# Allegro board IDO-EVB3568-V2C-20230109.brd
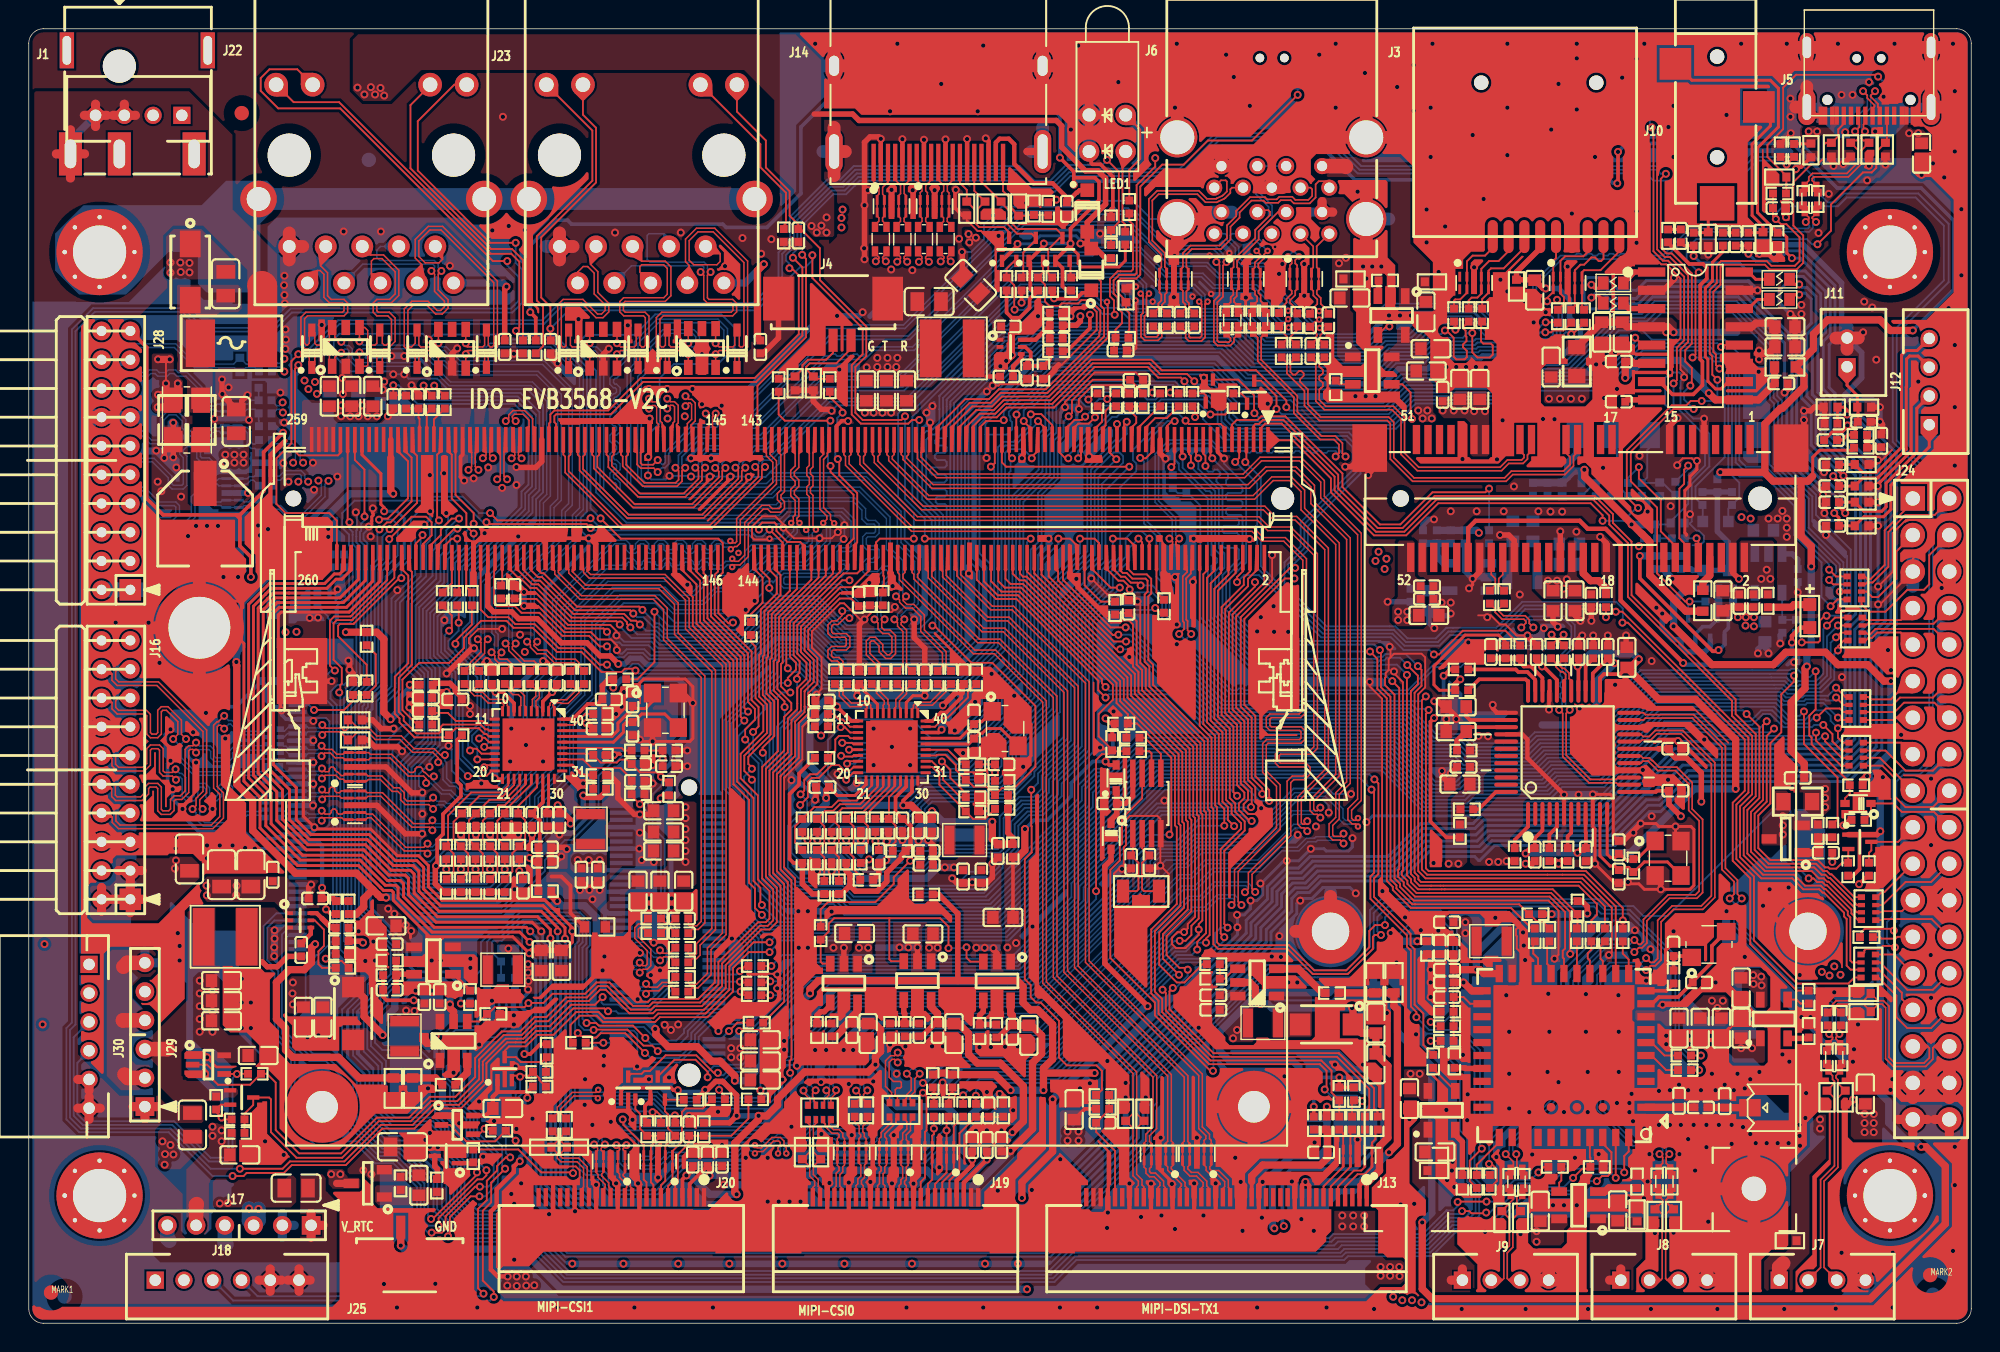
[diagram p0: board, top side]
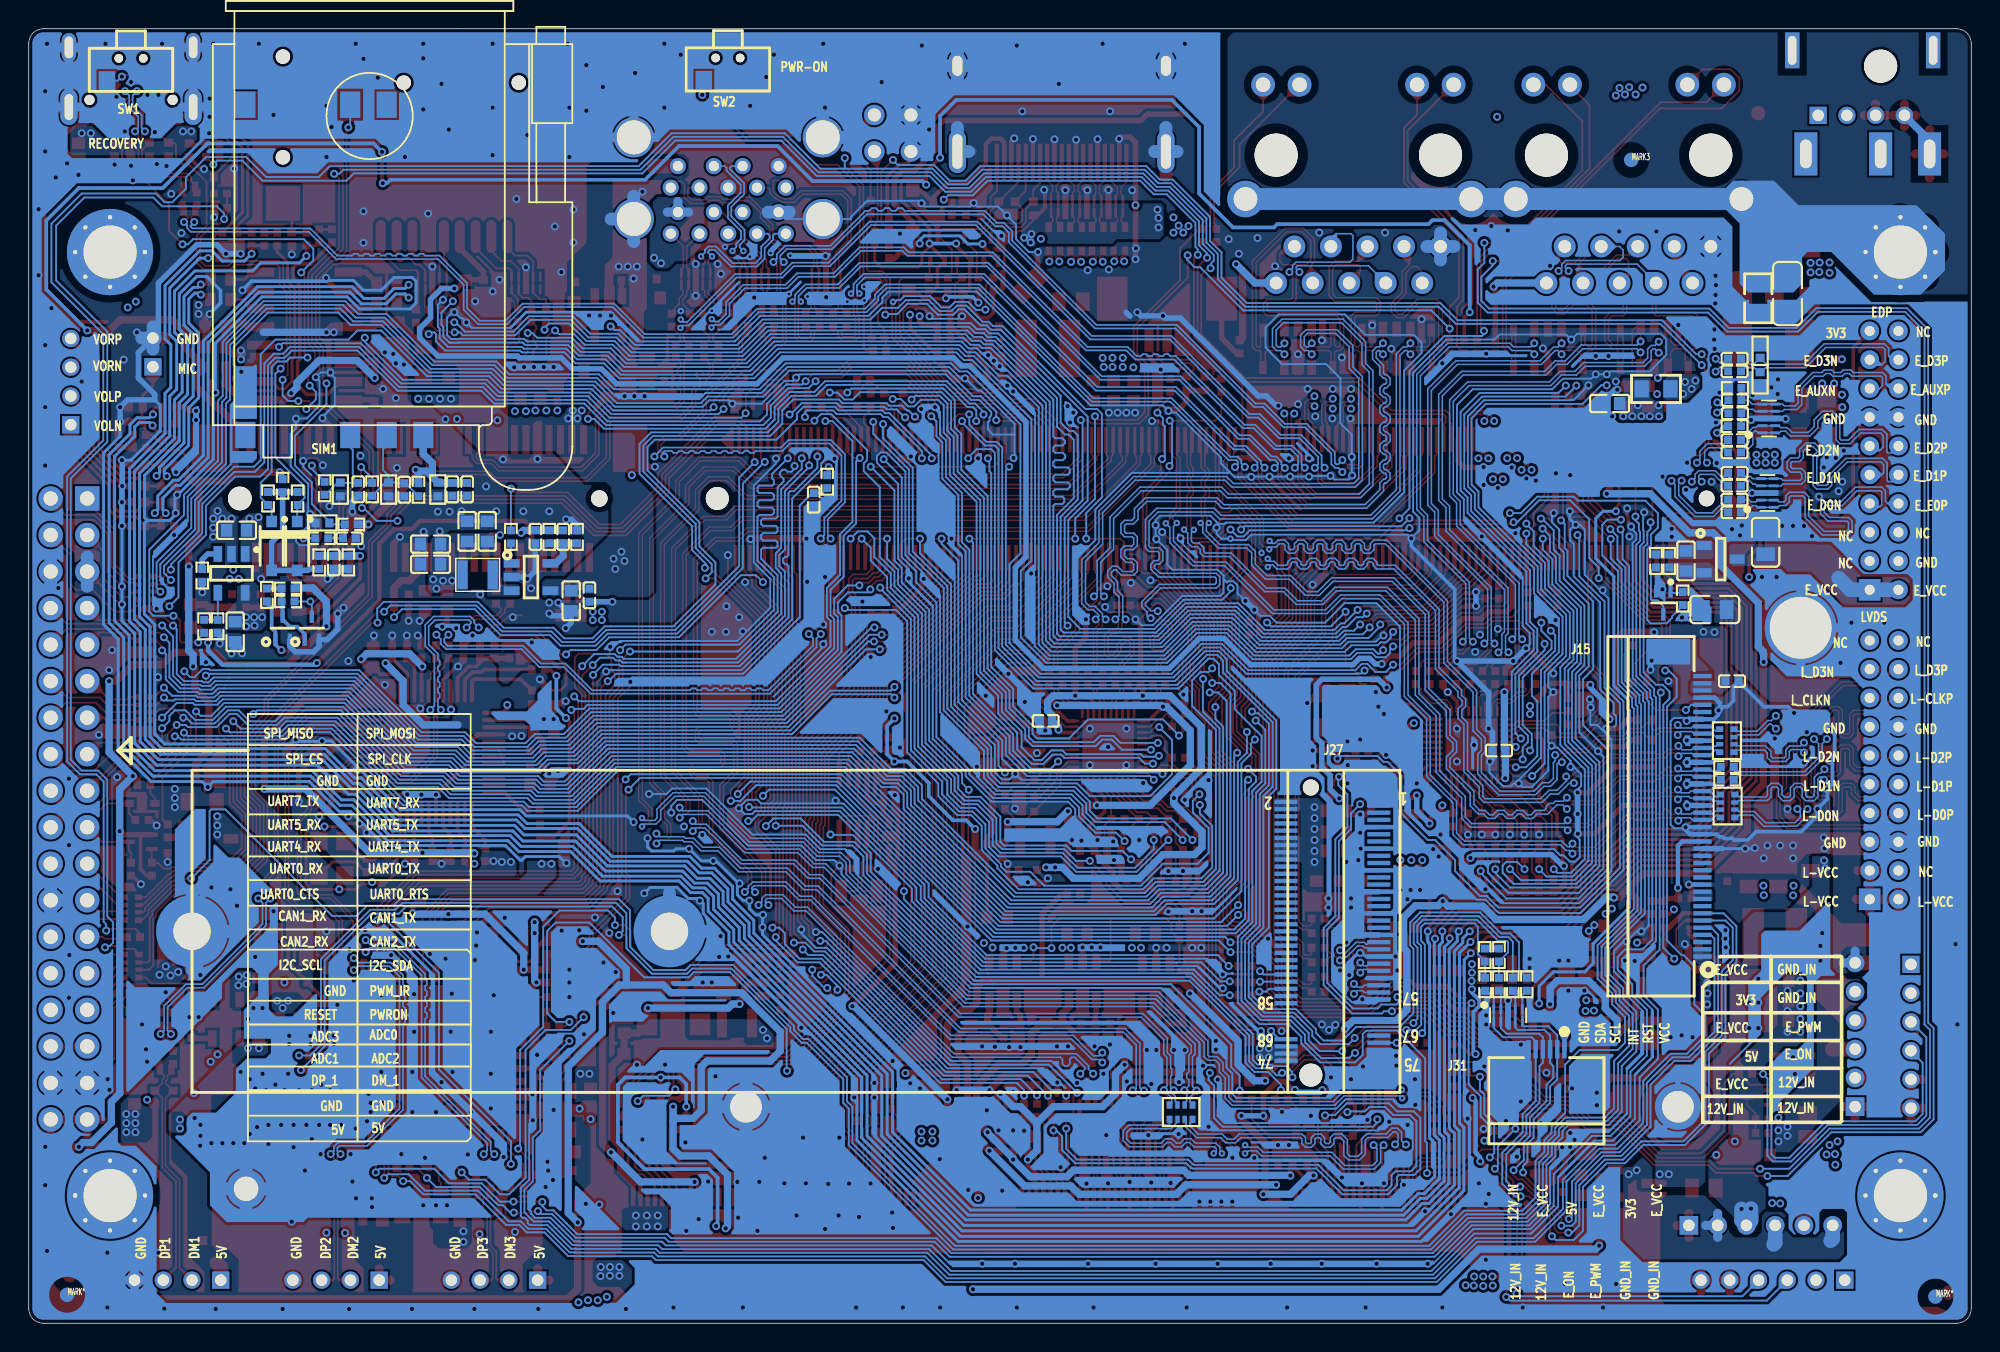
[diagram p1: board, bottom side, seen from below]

Outline 135.08 x 90.02 mm; copper layers: TOP, L2-GND, L3-POW, BOTTOM. Coordinates in mm from the lower left corner of the outline.
Outline path: 0,89 0,1.02 arc(0.3,0.3) 1.02,0 134.06,0 arc(134.78,0.3) 135.08,1.02 135.08,89 arc(134.78,89.72) 134.06,90.02 1.02,90.02 arc(0.3,89.72) 0,89

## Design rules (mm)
net group DIFFPAIR53: nets MIPI_CSI_D3N_ MIPI_CSI_D3P_
net group DIFFPAIR54: nets MIPI_CSI_D2N_ MIPI_CSI_D2P_
net group DIFFPAIR55: nets MIPI_CSI_D2N MIPI_CSI_D2P
net group DIFFPAIR56: nets MIPI_CSI_CLK0N MIPI_CSI_CLK0P
net group DIFFPAIR57: nets MIPI_CSI_D1N MIPI_CSI_D1P
net group DIFFPAIR58: nets MIPI_CSI_D0N MIPI_CSI_D0P
net group DIFFPAIR59: nets PCIE20_RXN_ PCIE20_RXP_
net group DIFFPAIR60: nets PCIE20_TXN_ PCIE20_TXP_
net group DIFFPAIR61: nets PCIE20_REFCLKN_ PCIE20_REFCLKP_
net group DIFFPAIR62: nets PCIE20_TX_N PCIE20_TX_P
net group DIFFPAIR63: nets LVDS_TX0_D0N LVDS_TX0_D0P
net group DIFFPAIR64: nets MIPI_DSI_TX0_D0N MIPI_DSI_TX0_D0P
net group DIFFPAIR65: nets LVDS_TX0_D1N LVDS_TX0_D1P
net group DIFFPAIR66: nets LVDS_TX0_CLKN LVDS_TX0_CLKP
net group DIFFPAIR67: nets LVDS_TX0_D2N LVDS_TX0_D2P
net group DIFFPAIR68: nets LVDS_TX0_D3N LVDS_TX0_D3P
net group DIFFPAIR77: nets MIPI_CSI_D3N MIPI_CSI_D3P
net group DIFFPAIR78: nets MIPI_DSI_TX1_D0N MIPI_DSI_TX1_D0P
net group DIFFPAIR87: nets MIPI_CSI_CLK1N MIPI_CSI_CLK1P
net group DIFFPAIR91: nets USB3_OTG0_DM_ USB3_OTG0_DP_
net group DIFFPAIR92: nets FE1_1_DM4 FE1_1_DP4
net group DP1: nets USB3_OTG0_SSRXN_ USB3_OTG0_SSRXP_
net group DP2: nets USB3_OTG0_SSTXN_ USB3_OTG0_SSTXP_
net group 90OHM: nets DM1_ DM2_ DM3_ DP1_ DP2_ DP3_ FE1_1_DM1 FE1_1_DM2 FE1_1_DM3 FE1_1_DP1 FE1_1_DP2 FE1_1_DP3 USB2_HOST2_DM USB2_HOST2_DM_ USB2_HOST2_DP USB2_HOST2_DP_ USB2_HOST3_DM USB2_HOST3_DP USB3_HOST1_DM USB3_HOST1_DM_ USB3_HOST1_DP USB3_HOST1_DP_ USB3_HOST1_SSRXN USB3_HOST1_SSRXN_ USB3_HOST1_SSRXP USB3_HOST1_SSRXP_ USB3_HOST1_SSTXN USB3_HOST1_SSTXN_ USB3_HOST1_SSTXP USB3_HOST1_SSTXP_ USB3_OTG0_DM USB3_OTG0_DP USB3_OTG0_SSRXN USB3_OTG0_SSRXP USB3_OTG0_SSTXN USB3_OTG0_SSTXP
net group 100OHM: nets EDP_TX_AUXN EDP_TX_AUXN_ EDP_TX_AUXP EDP_TX_AUXP_ EDP_TX_D0N EDP_TX_D0N_ EDP_TX_D0P EDP_TX_D0P_ EDP_TX_D1N EDP_TX_D1N_ EDP_TX_D1P EDP_TX_D1P_ EDP_TX_D2N EDP_TX_D2N_ EDP_TX_D2P EDP_TX_D2P_ EDP_TX_D3N EDP_TX_D3N_ EDP_TX_D3P EDP_TX_D3P_ HDMI_TX_CLKN HDMI_TX_CLKN_ HDMI_TX_CLKP HDMI_TX_CLKP_ HDMI_TX_D0N HDMI_TX_D0N_ HDMI_TX_D0P HDMI_TX_D0P_ HDMI_TX_D1N HDMI_TX_D1N_ HDMI_TX_D1P HDMI_TX_D1P_ HDMI_TX_D2N HDMI_TX_D2N_ HDMI_TX_D2P HDMI_TX_D2P_ LAN0_A+ LAN0_A- LAN0_B+ LAN0_B- LAN0_C+ LAN0_C- LAN0_D+ LAN0_D- LAN1_A+ LAN1_A- LAN1_B+ LAN1_B- LAN1_C+ LAN1_C- LAN1_D+ LAN1_D- MIPI_CSI_RX_CLK0N MIPI_CSI_RX_CLK0P MIPI_CSI_RX_CLK1N MIPI_CSI_RX_CLK1P MIPI_CSI_RX_D0N MIPI_CSI_RX_D0P MIPI_CSI_RX_D1N MIPI_CSI_RX_D1P MIPI_CSI_RX_D2N MIPI_CSI_RX_D2P MIPI_CSI_RX_D3N MIPI_CSI_RX_D3P MIPI_DSI_TX0_CLKN MIPI_DSI_TX0_CLKP MIPI_DSI_TX0_D1N MIPI_DSI_TX0_D1P MIPI_DSI_TX0_D2N MIPI_DSI_TX0_D2P MIPI_DSI_TX0_D3N MIPI_DSI_TX0_D3P MIPI_DSI_TX1_CLKN MIPI_DSI_TX1_CLKP MIPI_DSI_TX1_D1N MIPI_DSI_TX1_D1P MIPI_DSI_TX1_D2N MIPI_DSI_TX1_D2P MIPI_DSI_TX1_D3N MIPI_DSI_TX1_D3P PCIE20_REFCLKN PCIE20_REFCLKP PCIE20_RXN PCIE20_RXP PCIE20_TXN PCIE20_TXP PHY0_MDI0+ PHY0_MDI0- PHY0_MDI1+ PHY0_MDI1- PHY0_MDI2+ PHY0_MDI2- PHY0_MDI3+ PHY0_MDI3- PHY1_MDI0+ PHY1_MDI0- PHY1_MDI1+ PHY1_MDI1- PHY1_MDI2+ PHY1_MDI2- PHY1_MDI3+ PHY1_MDI3-
net group USB: nets 5G_SSRXN 5G_SSRXP 5G_SSTXN 5G_SSTXP DM4 DM_1 DP4 DP_1 FE1_1_DM0 FE1_1_DP0

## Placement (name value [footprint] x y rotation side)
C1  100nF  [C0402]  68 65.84 0 top
C2  10uF  [C0805]  13.69 72.29 270 top
C3  100uF/25V  [CAPAE660X770]  12.27 55.96 270 top
C4  10uF  [C0805]  14.43 62.71 270 top
C5  10uF  [C0805]  62.61 71.04 0 top
C6  10uF  [C0805]  65.5 72.19 315 top
C7  100nF  [C0402]  68.07 69.32 180 top
C8  100pF  [C0402]  71.45 68.48 0 top
C9  22uF  [C0603]  58.24 64.85 90 top
C10  22uF  [C0603]  61.04 64.85 90 top
C11  22uF  [C0603]  59.64 64.85 90 top
C12  100nF  [C0402]  69.42 66.12 90 top
C13  100nF  [C0402]  18.95 25.96 90 top
C14  10uF  [C0805]  13.41 31.19 270 top
C15  10uF  [C0805]  15.44 31.19 270 top
C16  100nF  [C0402]  16.97 31.19 270 top
C17  100pF  [C0402]  21.79 27.51 0 top
C18  22uF  [C0603]  13.41 22.43 180 top
C19  22uF  [C0603]  13.41 23.83 180 top
C20  22uF  [C0603]  13.41 21.03 180 top
C21  22uF  [C0603]  35.64 25.22 270 top
C22  10uF  [C0603]  24.84 27.64 0 top
C23  1uF  [C0402]  25.1 26.37 0 top
C24  47pF  [C0402]  25.1 23.19 180 top
C25  22uF  [C0603]  37.03 25.22 270 top
C26  22uF  [C0603]  25.15 63.96 180 bottom
C27  22uF  [C0603]  22.45 64.47 270 top
C28  22uF  [C0603]  23.93 64.47 270 top
C29  22uF  [C0603]  20.9 64.47 270 top
C30  6.8pF  [C0402]  33.78 50.85 270 top
C31  10uF  [C0603]  104.72 71.83 90 top
C32  10uF  [C0603]  131.62 81.36 90 top
C33  10uF  [C0603]  120.73 48.08 270 bottom
C34  10uF  [C0603]  120.62 55.14 0 bottom
C35  1uF  [C0402]  113.87 52.91 90 bottom
C36  10uF  [C0603]  97.16 70.33 270 top
C37  10uF  [C0603]  97.18 66.22 0 top
C38  10uF  [C0603]  91.87 71.3 0 top
C39  100nF  [C0402]  80.09 69.77 90 top
C40  10uF  [C0603]  97.51 67.77 0 top
C41  100nF  [C0402]  81.05 69.77 90 top
C42  10uF  [C0603]  119.08 20.52 90 top
C43  10uF  [C0603]  119.08 23.32 270 top
C44  10uF  [C0603]  99.26 41.15 0 top
C45  10uF  [C0603]  99.26 42.88 0 top
C46  10uF  [C0603]  110.49 7.82 90 top
C47  10uF  [C0603]  105.11 7.8 90 top
C48  NC/1uF  [C0402]  101.68 46.69 270 top
C49  18pF  [C0402]  110.57 33.1 270 top
C50  10uF  [C0603]  111.12 46.3 270 top
C51  18pF  [C0402]  110.57 31.06 90 top
C52  10uF  [C0603]  97.79 11.91 0 top
C53  10uF  [C0603]  96.01 15.62 270 top
C54  10uF  [C0603]  99.52 37.49 0 top
C55  100nF  [C0402]  104.85 46.69 270 top
C56  100nF  [C0402]  99.77 38.68 0 top
C57  100nF  [C0402]  114.5 37.03 180 top
C58  100nF  [C0402]  109.8 46.69 270 top
C59  100nF  [C0402]  114.5 39.95 180 top
C60  100nF  [C0402]  108.28 32.59 90 top
C61  100nF  [C0402]  104.72 32.59 90 top
C62  100nF  [C0402]  107.77 46.69 270 top
C63  1uF  [C0402]  128.83 61.37 90 top
C64  1uF  [C0402]  125.3 61.42 180 top
C65  220pF  [C0402]  127.63 62.69 180 top
C66  1uF  [C0402]  125.32 62.56 0 top
C67  100nF  [C0402]  110.57 66.88 0 top
C68  100nF  [C0402]  121.87 65.35 180 top
C71  1uF  [C0402]  110.57 64.08 0 top
C72  100nF  [C0402]  114.88 75.62 270 top
C73  1nF  [C0402]  125.43 55.45 180 top
C74  1nF  [C0402]  125.43 57.1 180 top
C75  100nF  [C0402]  118.69 75.39 270 top
C76  1nF  [C0402]  125.43 58.22 180 top
C77  1nF  [C0402]  125.43 59.72 180 top
C78  1uF  [C0402]  89.87 11.89 0 top
C79  10uF  [C0603]  72.69 14.86 270 top
C80  NC/1uF  [C0402]  74.68 13.94 180 top
C81  1uF  [C0603]  93.68 18.03 90 top
C82  100nF  [C0402]  82.37 21.79 0 top
C83  4.7uF  [C0402]  82.37 22.81 0 top
C84  1uF  [C0603]  93.68 20.88 270 top
C85  100nF  [C0402]  72.19 77.5 90 top
C86  1uF  [C0603]  20.45 21.29 90 top
C87  1uF  [C0603]  19.1 21.29 90 top
C88  100nF  [C0402]  28.57 22.68 270 top
C89  4.7uF  [C0402]  27.51 22.68 270 top
C90  NC/1uF  [C0402]  22.56 44.15 270 top
C91  10uF  [C0805]  25.98 12.27 180 top
C92  1uF  [C0603]  27.13 9.6 90 top
C93  10uF  [C0805]  11.18 32.28 270 top
C94  NC/1uF  [C0603]  32.97 14.94 180 top
C95  NC/6.8pF  [C0402]  76.48 49.83 270 top
C96  100nF  [C0402]  66.75 14.81 270 top
C97  NC/6.8pF  [C0402]  57.71 50.32 270 top
C98  100nF  [C0402]  48.21 11.38 270 top
C99  100nF  [C0402]  45.92 13.49 270 top
C100  100nF  [C0402]  47.19 11.38 270 top
C101  10uF  [C0603]  57.43 27.1 0 top
C102  10uF  [C0603]  58.37 20.14 90 top
C103  100nF  [C0402]  57.25 20.4 90 top
C104  100nF  [C0402]  46.18 11.38 270 top
C105  10uF  [C0603]  62.18 27.08 0 top
C106  10uF  [C0603]  64.34 20.14 90 top
C107  100nF  [C0402]  63.2 20.4 90 top
C108  NC/18pF  [C0402]  61.93 20.4 90 top
C109  10uF  [C0603]  67.74 28.22 0 top
C110  10uF  [C0603]  69.55 20.02 90 top
C111  100nF  [C0402]  68.4 20.27 90 top
C112  NC/6.8pF  [C0402]  80.49 57.28 90 bottom
C113  10pF  [C0402]  116.28 15.01 180 top
C114  NC/18pF  [C0402]  116.15 23.7 0 top
C115  NC/10pF  [C0402]  114.76 15.47 270 top
C116  NC/10pF  [C0402]  117.93 15.44 270 top
C117  NC/18pF  [C0402]  114.38 25.98 270 top
C118  22uF  [C0603]  116.23 20.52 90 top
C119  22uF  [C0603]  117.7 20.52 90 top
C120  1uF  [C0402]  99.09 26.11 270 top
C121  1uF  [C0402]  98.63 24.59 0 top
C122  100nF  [C0402]  98.12 26.11 270 top
C123  100nF  [C0402]  123.01 37.92 0 top
C124  1uF  [C0402]  124.97 32.72 0 top
C125  10uF  [C0603]  114.76 20.52 90 top
C126  NC/6.8pF  [C0402]  98.63 22.68 0 top
C127  4.7uF  [C0402]  98.63 27.89 0 top
C128  100nF  [C0402]  98.63 23.7 0 top
C129  18pF  [C0402]  41.99 43.38 270 top
C130  18pF  [C0402]  41.99 41.35 90 top
C131  NC/6.8pF  [C0402]  44.53 38.73 180 top
C132  NC/100pF  [C0402]  42.37 38.89 180 top
C133  NC/100pF  [C0402]  42.37 37.72 180 top
C134  NC/6.8pF  [C0402]  27.1 64.06 270 top
C135  NC/6.8pF  [C0402]  25.35 64.06 90 top
C136  4.7uF  [C0402]  39.57 31.19 90 top
C137  100nF  [C0402]  38.43 31.19 90 top
C138  100nF  [C0402]  32.84 39.83 180 bottom
C139  100nF  [C0402]  39.7 41.35 180 top
C140  100nF  [C0402]  32.21 44.91 270 top
C141  100nF  [C0402]  36.73 44.91 270 top
C142  10nF  [C0402]  33.1 67.89 90 top
C143  100nF  [C0402]  27.61 42.57 0 top
C144  1uF  [C0402]  35.89 32.08 180 top
C145  1uF  [C0402]  35.89 33.1 180 top
C146  100nF  [C0402]  35 35 90 top
C147  NC/6.8pF  [C0402]  34.37 30.43 90 top
C148  4.7uF  [C0402]  27.61 43.48 0 top
C149  100nF  [C0402]  40.34 43.38 180 top
C150  100nF  [C0402]  29.67 43.38 0 top
C151  4.7uF  [C0402]  36.07 35 90 top
C152  100nF  [C0402]  36.91 35 90 top
C153  18pF  [C0402]  65.74 40.21 90 top
C154  18pF  [C0402]  65.74 42.11 270 top
C155  NC/6.8pF  [C0402]  67.64 38.86 180 top
C156  NC/100pF  [C0402]  36.3 67.89 90 top
C157  NC/100pF  [C0402]  53.52 75.64 90 top
C158  NC/6.8pF  [C0402]  76.53 64.21 270 top
C159  NC/6.8pF  [C0402]  77.04 65.61 180 top
C160  4.7uF  [C0402]  66.24 31.06 90 top
C161  100nF  [C0402]  64.97 31.06 90 top
C162  100nF  [C0402]  55.19 37.29 0 top
C163  100nF  [C0402]  64.36 41.88 180 bottom
C164  100nF  [C0402]  62.31 44.91 90 top
C165  100nF  [C0402]  57.76 44.91 270 top
C166  10nF  [C0402]  50.88 67.89 90 top
C167  100nF  [C0402]  55.12 42.37 0 top
C168  1uF  [C0402]  62.43 31.88 0 top
C169  1uF  [C0402]  62.43 32.84 180 top
C170  100nF  [C0402]  60.76 34.62 90 top
C171  NC/6.8pF  [C0402]  59.11 32.46 90 top
C172  4.7uF  [C0402]  67.39 32.84 90 top
C173  100nF  [C0402]  65.02 44.91 270 top
C174  100nF  [C0402]  55.14 43.31 0 top
C175  4.7uF  [C0402]  61.87 34.62 90 top
C176  100nF  [C0402]  62.81 34.62 270 top
C177  10uF  [C0603]  127.71 15.95 90 top
C179  18pF  [C0402]  76.66 32.08 90 top
C180  18pF  [C0402]  77.93 32.08 90 top
C181  1uF  [C0402]  75.21 36.14 0 top
C182  100nF  [C0402]  121.74 77.55 180 top
C183  100nF  [C0402]  104.6 57.99 270 bottom
C184  33pF  [C0402]  108.97 57.96 270 bottom
C185  33pF  [C0402]  112.17 57.99 270 bottom
C186  100nF  [C0402]  105.61 57.99 270 bottom
C187  NC/100nF  [C0402]  89.18 67.61 270 top
C188  33pF  [C0402]  112.78 54.58 180 bottom
C189  NC/100nF  [C0402]  90.09 67.61 270 top
C190  22uF  [C0603]  105.99 50.24 90 top
C191  22uF  [C0603]  103.2 55.07 270 bottom
C192  22uF  [C0603]  104.6 55.07 270 bottom
C193  22uF  [C0603]  97.36 49.23 180 top
C194  33pF  [C0402]  97.23 50.37 180 top
C195  22uF  [C0603]  107.52 50.24 90 top
C196  22uF  [C0603]  107.14 52.78 180 bottom
C197  22uF  [C0603]  107.14 54.18 180 bottom
C198  22uF  [C0603]  99.52 64.95 270 top
C199  33pF  [C0402]  118.95 50.24 90 top
C200  100nF  [C0402]  119.94 50.24 90 top
C201  10pF  [C0402]  98.32 64.57 270 top
C202  33pF  [C0402]  108.66 50.24 90 top
C203  100nF  [C0402]  99.85 54.69 90 bottom
C204  10pF  [C0402]  97.23 51.26 180 top
C205  10uF  [C0603]  97.36 50.24 90 bottom
C206  1uF  [C0402]  96.09 50.62 90 bottom
C207  6.8pF  [C0402]  97.92 54.69 90 bottom
C208  22uF  [C0603]  100.9 64.94 270 top
C209  22uF  [C0603]  117.81 50.24 90 top
C212  100nF  [C0402]  45.42 28.14 180 top
C213  100nF  [C0402]  45.42 27.13 180 top
C214  22uF  [C0603]  43.89 30.05 90 top
C215  22uF  [C0603]  50.88 18.24 180 top
C216  22uF  [C0603]  50.88 19.71 180 top
C217  22uF  [C0603]  44.15 35.64 0 top
C218  22uF  [C0603]  45.54 30.05 90 top
C219  22uF  [C0603]  50.88 16.92 180 top
C220  22uF  [C0603]  42.37 30.05 90 top
C221  22uF  [C0603]  44.15 32.84 0 top
C222  22uF  [C0603]  44.15 34.16 0 top
C233  100nF  [C0402]  16.46 66.19 0 bottom
C234  100nF  [C0402]  16.46 67.08 0 bottom
C235  100nF  [C0402]  16.43 63.27 0 bottom
C236  100nF  [C0402]  16.43 64.19 0 bottom
C237  100nF  [C0402]  16.46 60.55 0 bottom
C238  100nF  [C0402]  16.46 61.42 0 bottom
C239  100nF  [C0402]  16.46 58.24 0 bottom
C240  100nF  [C0402]  16.46 59.13 0 bottom
C241  100nF  [C0402]  16.46 56.39 0 bottom
C242  100nF  [C0402]  16.46 57.28 0 bottom
C243  10uF  [C0603]  14.68 11.71 180 top
C244  NC/1uF  [C0603]  15.95 18.62 180 top
C245  10uF  [C0805]  17.83 49.63 180 bottom
C246  1uF  [C0603]  19.84 53.01 270 bottom
C247  10uF  [C0805]  14.3 54.31 270 bottom
C248  22uF  [C0603]  105.87 66.5 270 top
C249  22uF  [C0603]  122.12 69.29 180 top
C250  22uF  [C0603]  109.37 68.91 90 top
C251  22uF  [C0603]  110.82 68.91 90 top
C252  22uF  [C0603]  122.12 67.89 180 top
C253  1uF  [C0402]  67.64 12.4 270 top
C254  1uF  [C0402]  66.62 12.4 270 top
C255  1uF  [C0402]  65.61 12.4 270 top
C256  10uF  [C0805]  18.59 9.4 0 top
C257  10uF  [C0805]  11.38 13.79 90 top
C258  1uF  [C0402]  19.91 29.54 0 top
C259  100nF  [C0402]  75.92 67.64 180 top
C260  1uF  [C0402]  16.64 44.65 0 bottom
C261  1nF  [C1206]  12.78 71.6 90 bottom
C290  100nF  [C0402]  89.1 69.75 90 top
C291  100nF  [C0402]  90.37 69.75 90 top
D1  SMAJ16CA  [SMA_DO-214AC]  11.23 73.1 270 top
D2  PE0402N12G01B  [V0402]  103.45 72.09 90 top
D3  SE05NRC14GA  [DFN2510-10L]  100.51 72.34 0 top
D4  SE05NRC14GA  [DFN2510-10L]  107.01 72.34 0 top
D5  PE0402N12G01B  [V0402]  54.56 65.35 90 top
D6  PE0402N12G01B  [V0402]  53.29 65.35 90 top
D7  PE0402N12G01B  [V0402]  123.93 81.56 90 top
D8  PE0402N12G01B  [V0402]  129.11 81.61 90 top
D9  PE0402N12G01B  [V0402]  125.35 81.61 90 top
D10  PE0402N12G01B  [V0402]  126.7 81.61 90 top
D11  B5819W-G  [SOD123]  118.19 54.05 270 bottom
D12  PE0402N12G01B  [V0402]  127.97 81.61 90 top
D13  B5819W-G  [SOD123]  116.41 54.05 270 bottom
D14  SE05NRC14GA  [DFN2510-10L]  84.63 72.62 0 top
D15  PE0402N12G01B  [V0402]  97.56 72.42 0 top
D16  PE0402N12G01B  [V0402]  91.9 72.62 0 top
D17  SE05NRC14GA  [DFN2510-10L]  88.7 72.62 0 top
D18  PE0402N12G01B  [V0402]  125.04 15.7 90 top
D19  PE0402N12G01B  [V0402]  122.45 5.74 0 top
D20  PE0402N12G01B  [V0402]  126.31 15.7 90 top
D21  PE0402N12G01B  [V0402]  111.84 7.57 270 top
D22  PE0402N12G01B  [V0402]  114.38 7.44 90 top
D23  PE0402N12G01B  [V0402]  113.08 7.44 90 top
D24  PE0402N12G01B  [V0402]  97.74 10.62 180 top
D25  PE0402N12G01B  [V0402]  102.44 7.32 90 top
D26  PE0402N12G01B  [V0402]  103.73 7.32 90 top
D27  PE0402N12G01B  [V0402]  120.6 75.39 90 top
D28  PE0402N12G01B  [V0402]  116.79 75.39 90 top
D29  PE0402N12G01B  [V0402]  127.63 63.7 180 top
D30  PE0402N12G01B  [V0402]  127.46 55.45 180 top
D31  PE0402N12G01B  [V0402]  127.46 57.1 180 top
D32  PE0402N12G01B  [V0402]  127.46 58.22 180 top
D33  PE0402N12G01B  [V0402]  127.46 59.72 180 top
D34  SE05NRC14GA  [DFN2510-10L]  92.41 11.63 180 top
D35  SE05NRC14GA  [DFN2510-10L]  81.23 11.76 180 top
D36  PE0402N12G01B  [V0402]  77.55 14.55 90 top
D37  SE05NRC14GA  [DFN2510-10L]  78.56 11.76 180 top
D38  PE0402N12G01B  [V0402]  76.28 14.55 90 top
D39  SM340AF  [SMAF]  90.25 20.78 0 top
D40  SE05NRC14GA  [DFN2510-10L]  59.99 77.67 0 top
D41  SE05NRC14GA  [DFN2510-10L]  62.99 77.67 0 top
D42  LMBR140FT1G  [SOD-123F]  73.89 73.28 270 top
D43  LMBR140FT1G  [SOD-123F]  73.61 77.34 90 top
D44  PE0402N12G01B  [V0402]  65.23 77.52 270 top
D45  PE0402N12G01B  [V0402]  66.5 77.52 270 top
D46  PE0402N12G01B  [V0402]  68.83 77.5 90 top
D47  PE0402N12G01B  [V0402]  67.61 77.52 270 top
D48  SE05NRC14GA  [DFN2510-10L]  32.21 21.41 180 bottom
D49  SE05NRC14GA  [DFN2510-10L]  22.68 36.02 90 top
D50  SM340AF  [SMAF]  22.56 21.54 90 top
D51  SE05NRC14GA  [DFN2510-10L]  22.68 38.68 90 top
D52  PE0402N12G01B  [V0402]  22.68 40.56 0 top
D53  PE0402N12G01B  [V0402]  22.68 41.96 0 top
D54  SE05D3L01GE  [SOD323]  19.69 67.77 90 top
D55  SE05D3L01GE  [SOD323]  24.41 67.77 90 top
D56  SE05D3L01GE  [SOD323]  27 67.77 90 top
D57  SE05D3L01GE  [SOD323]  31.83 67.77 90 top
D58  SE05D3L01GE  [SOD323]  37.54 67.77 90 top
D59  SE05D3L01GE  [SOD323]  42.37 67.77 90 top
D60  SE05D3L01GE  [SOD323]  44.4 67.77 90 top
D61  SE05D3L01GE  [SOD323]  49.25 67.77 90 top
D64  PE0402N12G01B  [V0402]  127.61 21.67 180 top
D65  PE0402N12G01B  [V0402]  127.61 22.94 180 top
D69  LRB520S-30T1G  [SOD523]  75.62 37.92 90 top
D70  LRB520S-30T1G  [SOD523]  75.26 33.86 270 top
D71  ES0402V014CT  [V0402]  121.74 79.71 180 top
D72  ES0402V014CT  [V0402]  110.06 57.99 270 bottom
D73  ES0402V014CT  [V0402]  114.66 55.65 0 bottom
D74  ES0402V014CT  [V0402]  106.63 57.99 270 bottom
D75  ES0402V014CT  [V0402]  113.41 57.99 270 bottom
D76  SE05NRC14GA  [DFN2510-10L]  14.17 57.73 90 bottom
D77  SE05NRC14GA  [DFN2510-10L]  14.07 62.92 90 bottom
D79  PE0402N12G01B  [V0402]  14.68 67.61 90 bottom
D80  PE0402N12G01B  [V0402]  14.68 65.66 270 bottom
D81  SRV05-4  [SOT23-6]  39.95 67.77 90 top
D82  SRV05-4  [SOT23-6]  46.81 67.82 90 top
D83  SRV05-4  [SOT23-6]  22.05 67.89 90 top
D84  SRV05-4  [SOT23-6]  29.44 67.77 90 top
D90  LRB520S-30T1G  [SOD523]  127.2 36.14 180 top
D96  ES0402V014CT  [V0402]  76.3 71.48 90 top
D97  PE0402N12G01B  [V0402]  125.3 63.7 0 top
D98  SE05NRC14GA  [DFN2510-10L]  60.15 11.89 180 top
D99  SE05NRC14GA  [DFN2510-10L]  57.23 11.89 180 top
D100  PE0402N12G01B  [V0402]  55.07 11.89 90 top
D101  PE0402N12G01B  [V0402]  53.8 11.89 90 top
D102  SE05NRC14GA  [DFN2510-10L]  63.32 11.89 180 top
D103  SE05NRC14GA  [DFN2510-10L]  43.76 11.25 180 top
D104  SE05NRC14GA  [DFN2510-10L]  40.46 11.25 180 top
D105  PE0402N12G01B  [V0402]  37.9 12.24 0 top
D106  PE0402N12G01B  [V0402]  35.86 12.24 180 top
D107  SE05NRC14GA  [DFN2510-10L]  79.63 72.62 0 top
F2  FUSE_16V/2.6A  [SMD1812]  14.1 68.15 180 top
H1  HOLE  [4G_MTG170_450]  119.96 9.35 0 top
H2  HOLE  [MTG430_620_SMTSO_M3]  11.86 48.36 0 top
HOLE1  -  [MTG370_600_VIA]  4.92 74.49 180 bottom
HOLE2  -  [MTG370_600_VIA]  129.42 8.88 0 top
HOLE3  -  [MTG370_600_VIA]  4.92 8.88 180 bottom
HOLE4  -  [MTG370_600_VIA]  129.42 74.49 180 bottom
J1  DC-044A-2_5  [DC-044A-2_0-DIP]  6.3 91.52 270 top
J2  ATMD097-AED4S-5F  [DDR4-SODIMM-260P-STD]  87.2 57.35 180 top
J3  SD  [TF-01A]  101.8 75.77 180 top
J4  MX1.25T-S-3A  [MX125T-S-3A]  55.93 68.35 180 top
J5  TYPE-C-SMD  [USB_SMD-TYPE-C-16P]  127.97 88.72 180 top
J6  USB-9AFx2-DIP  [USB-9AF-DIP_2X]  86.44 80.47 180 top
J7  PH2.0-4A  [PH200-4A]  124.72 3 180 top
J8  PH2.0-4A  [PH200-4A]  113.71 3 180 top
J9  PH2.0-4A  [PH200-4A]  102.69 3 180 top
J10  PJ-326  [PJ-326A-3P]  114.5 87.58 270 top
J11  PH2.0-2A  [PH200-2A]  126.44 67.51 270 top
J12  PH2.0-4A  [PH200-4A]  132.16 65.48 270 top
J13  FPC05-PUW-40P  [FPC05-40P]  83.29 7.19 0 top
J14  -  [HDMI-TYPEA_SMD]  58.75 80.72 0 top
J15  FPC05-PUW-40P  [FPC05-40P]  20.27 35.26 270 bottom
J16  -  [HDR200MRA-2X10]  7.06 29.48 90 top
J17  -  [HDR200MA-1X6]  19.63 6.81 180 top
J18  PH2.0-6A  [PH200-6A]  13.79 3 180 top
J19  FPC05-PUW-24P  [FPC05-24P]  60.27 7.19 0 top
J20  FPC05-PUW-24P  [FPC05-24P]  41.21 7.19 0 top
J21  IPEX  [IPEX-001E]  121.49 14.99 180 top
J22  HR911130C  [RJ45-TH_HR911130A]  23.83 81.23 0 top
J23  HR911130C  [RJ45-TH_HR911130A]  42.62 81.23 0 top
J24  HDR254MA-2X20  [HDR254MA-2X18]  131.01 57.35 270 top
J25  MX1.25T-S-2A  [MX125T-S-2A]  26.49 6.68 0 top
J26  MINI-PCIE-S52-H80  [M_MINIPCIE_SOCKET_CK]  107.9 57.35 0 top
J27  -  [M2_NGFF-M-KEY]  45.92 27.25 0 bottom
J28  -  [HDR200MRA-2X10]  7.06 51 90 top
J29  -  [HDR200MA-1X6]  8.08 15.06 90 top
J30  PH2.0-6AW  [PH200-6AW]  4.19 19.96 90 top
J31  FPC05-FDW-6P  [FPC05-6P]  29.54 17.48 180 bottom
J32  PH2.0-4A  [PH200-4A]  7.65 84 0 top
L1  NC/ZCM1812D601PT-NM-HF  [CMLP-ACM4532]  11 62.81 270 top
L2  2.2uH/4.3A  [IND_404020]  64.21 67.79 180 top
L3  2.2uH/4.3A  [IND_404020]  13.67 26.87 180 top
L4  1uH/3A  [IND_252012]  32.97 24.59 0 top
L5  NC/WCM2012F2SF-900T04  [CMLS-ACM2012]  123.9 78.18 90 top
L6  NC/WCM2012F2SF-900T04  [CMLS-ACM2012]  85.55 69.8 90 top
L7  NC/WCM2012F2SF-900T04  [CMLS-ACM2012]  83.69 69.75 90 top
L8  NC/WCM2012F2SF-900T04  [CMLS-ACM2012]  125.55 18.49 270 top
L9  NC/WCM2012F2SF-900T04  [CMLS-ACM2012]  113.74 9.86 270 top
L10  NC/WCM2012F2SF-900T04  [CMLS-ACM2012]  103.45 9.83 270 top
L11  UPZ1608E101-3R0TF  [L0603]  110.19 70.94 180 top
L12  UPZ1608E101-3R0TF  [L0603]  110.19 72.34 180 top
L13  UPZ1608E101-3R0TF  [L0603]  121.74 71.2 0 top
L14  UPZ1608E101-3R0TF  [L0603]  121.74 72.59 0 top
L15  4.7uH/1.25A  [IND_252012]  85.83 20.88 0 top
L16  WCM2012F2SF-900T04  [CMLS-ACM2012]  59.25 75.39 90 top
L17  WCM2012F2SF-900T04  [CMLS-ACM2012]  60.74 75.39 90 top
L18  WCM2012F2SF-900T04  [CMLS-ACM2012]  62.24 75.39 90 top
L19  WCM2012F2SF-900T04  [CMLS-ACM2012]  63.75 75.39 90 top
L20  4.7uH/1.25A  [IND_252012]  26.14 19.96 270 top
L21  4.7uH/1.25A  [IND_252012]  101.73 26.57 180 top
L22  2.2uH/1.9A  [IND_252012]  39.07 34.37 270 top
L23  2.2uH/1.9A  [IND_252012]  65.07 33.6 0 top
L24  1uH/3A  [IND_252012]  103.86 52.04 0 bottom
LED1  LEDx2(R+G)  [LED_P254_2X2DIP]  75.01 82.75 180 top
LED2  Green LED0603  [LED0603]  123.85 49.17 270 top
MARK1  FID10X20  [FID1_0X2_3]  1.55 2.13 0 top
MARK2  FID10X20  [FID1_0X2_3]  132.22 3.35 0 top
MARK3  FID10X20  [FID1_0X2_3]  23.65 80.9 180 bottom
MARK4  FID10X20  [FID1_0X2_3]  14.81 84.15 0 top
MARK*  -  [unnamed]  132.41 1.98 180 bottom
MARK*#2  -  [unnamed]  2.49 1.85 180 bottom
Q1  MMFTN3019E  [SOT523]  115.39 48.34 90 bottom
Q2  MMFTN3019E  [SOT523]  117.42 48.34 90 bottom
Q3  MMFTN3019E  [SOT523]  70.03 74.68 90 top
Q4  MMFTN3019E  [SOT523]  71.88 74.68 90 top
Q5  MMFTN3019E  [SOT523]  68.17 74.68 90 top
Q6  CJ3401  [SOT23]  23.57 9.73 180 top
Q7  NC/MMFTN3019E  [SOT523]  33.1 17.7 90 top
Q8  MMFTN3019E  [SOT523]  29.03 11.63 180 top
Q10  CJ3401  [SOT23]  122.17 33.68 180 top
Q11  NC/MMFTN3019E  [SOT523]  14.81 15.7 0 top
Q12  CJ3401  [SOT23]  17.42 53.14 180 bottom
Q13  MMFTN3019E  [SOT523]  21.41 50.09 270 bottom
Q14  MMFTN3019E  [SOT523]  85.22 64.74 90 top
Q15  MMFTN3019E  [SOT523]  82.35 64.82 90 top
Q16  MMFTN3019E  [SOT523]  41.68 16.36 90 top
Q17  MMFTN3019E  [SOT523]  43.74 16.36 90 top
Q19  MMFTN3019E  [SOT523]  127.33 33.48 0 top
R1  0R  [R0805]  12.01 62.81 270 top
R2  0R  [R0805]  9.98 62.81 270 top
R3  100K  [R0402]  71.45 67.59 0 top
R4  105K  [R0402]  71.45 69.39 0 top
R5  47K  [R0402]  70.56 66.12 90 top
R6  20K  [R0402]  71.45 70.28 180 top
R7  47K  [R0402]  75.26 74.52 270 top
R8  1K  [R0402]  76.53 77.62 90 top
R9  15K  [R0402]  75.26 76.48 270 top
R10  1K  [R0402]  76.25 75.46 90 top
R11  105K  [R0402]  21.79 26.57 0 top
R12  20K  [R0402]  21.79 25.68 180 top
R13  1K  [R0402]  21.79 24.71 180 top
R14  1K  [R0402]  30.68 22.68 90 top
R15  45K  [R0402]  25.1 24.21 180 top
R16  10K  [R0402]  25.1 25.22 0 top
R17  0R  [R0805]  21.92 64.97 0 bottom
R18  22R  [R0402]  99.11 70.1 90 top
R19  22R  [R0402]  100.13 70.1 90 top
R20  22R  [R0402]  101.07 70.1 90 top
R21  22R  [R0402]  32.84 50.85 270 top
R22  22R  [R0402]  106.32 70.03 90 top
R23  22R  [R0402]  107.26 70.03 90 top
R24  22R  [R0402]  108.15 70.03 90 top
R25  100R  [R0402]  55.7 65.23 90 top
R26  100R  [R0402]  52.15 65.23 90 top
R27  10K  [R0402]  122.76 81.56 270 top
R28  15K  [R0402]  121.82 81.56 270 top
R29  2.2R  [R0402]  124.41 78.18 90 top
R30  100K  [R0402]  117.04 51.1 180 bottom
R31  NC/0R  [R0402]  117.04 50.19 180 bottom
R32  22R  [R0402]  122.89 48.46 90 bottom
R33  6.8K  [R0402]  123.01 51.99 90 bottom
R34  2.2R  [R0402]  123.39 78.18 90 top
R35  NC/0R  [R0402]  118.52 50.65 90 bottom
R36  510K  [R0402]  121.95 48.46 90 bottom
R37  68K  [R0402]  117.42 58.24 90 bottom
R38  NC/0R  [R0402]  118.44 57.35 90 bottom
R39  33K  [R0402]  114.88 52.91 90 bottom
R40  NC/0R  [R0402]  116.38 57.35 90 bottom
R41  220K  [R0402]  112.85 52.91 90 bottom
R42  2.2R  [R0402]  86.03 69.8 90 top
R43  2.2R  [R0402]  85.06 69.8 90 top
R45  6.8K  [R0402]  94.31 72.52 180 top
R46  2.2R  [R0402]  84.12 69.8 90 top
R47  2.2R  [R0402]  83.26 69.8 90 top
R48  2.2R  [R0402]  78.21 69.77 90 top
R49  2.2R  [R0402]  79.15 69.77 90 top
R51  6.8K  [R0402]  90.88 65.1 90 top
R52  2.2R  [R0402]  125.04 18.49 270 top
R53  0R  [R0402]  103.71 46.69 270 top
R54  10K  [R0402]  105.74 32.59 270 top
R55  10K  [R0402]  107.01 32.59 270 top
R56  2.2R  [R0402]  126.06 18.49 270 top
R57  22R  [R0402]  123.77 22.68 270 top
R58  10K  [R0402]  103.33 32.59 270 top
R59  10K  [R0402]  100 35.74 0 top
R60  6.8K  [R0402]  123.77 20.32 270 top
R61  0R  [R0402]  99.77 39.83 0 top
R64  2.2R  [R0402]  113.23 9.86 270 top
R65  10K  [R0402]  99.64 44.02 0 top
R66  NC/10K  [R0402]  102.69 46.69 90 top
R67  2.2R  [R0402]  114.25 9.86 270 top
R68  1M  [R0402]  111.58 31.83 270 top
R69  0R  [R0402]  105.87 46.69 90 top
R70  22R  [R0402]  106.12 10.87 0 top
R71  0R  [R0402]  106.76 46.69 90 top
R72  6.8K  [R0402]  111.84 9.86 270 top
R73  2.7K  [R0402]  108.79 46.69 90 top
R74  47K  [R0402]  99.64 45.47 180 top
R75  2.2R  [R0402]  102.95 9.83 270 top
R76  0R  [R0402]  99.52 34.24 90 top
R77  22R  [R0402]  97.66 18.21 270 top
R78  2.2R  [R0402]  103.96 9.83 270 top
R79  6.8K  [R0402]  99.7 9.86 90 top
R80  100R  [R0402]  127.38 60.88 0 top
R81  0R  [R0402]  121.62 75.39 270 top
R82  0R  [R0402]  119.58 75.39 90 top
R83  4.7K  [R0402]  127.38 61.77 0 top
R84  0R  [R0402]  115.77 75.39 90 top
R85  0R  [R0603]  122.12 66.5 180 top
R86  0R  [R0805]  107.65 66.88 90 top
R87  30K  [R0402]  114 75.62 270 top
R88  30K  [R0402]  117.81 75.39 270 top
R89  1K  [R0402]  80.92 64.21 90 top
R90  1K  [R0402]  83.77 64.21 90 top
R91  22R  [R0402]  82.37 24.97 0 top
R92  2.2K  [R0402]  92.15 15.95 90 top
R93  2.2K  [R0402]  91.14 15.95 90 top
R94  22R  [R0402]  93.8 13.92 270 top
R95  22R  [R0402]  92.91 13.92 270 top
R96  22R  [R0402]  92.02 13.92 270 top
R97  22R  [R0402]  91.14 13.92 270 top
R98  NC/10K  [R0402]  74.68 14.91 0 top
R99  100K  [R0402]  90.63 22.96 180 top
R100  100K  [R0402]  82.37 23.95 0 top
R101  3.9R  [R0603]  94.93 23.7 270 top
R102  3.9R  [R0603]  93.6 23.7 270 top
R103  10K  [R0402]  70.18 72.26 90 top
R104  1.8K  [R0402]  69.04 72.26 270 top
R105  10K  [R0402]  72.49 72.26 90 top
R106  1.8K  [R0402]  71.17 72.26 90 top
R107  1K  [R0402]  70.89 77.5 270 top
R108  100K  [R0402]  69.9 77.52 270 top
R109  27K  [R0402]  68 72.26 270 top
R110  22R  [R0402]  50.22 48.31 270 top
R111  2.2K  [R0402]  32.84 25.6 90 bottom
R112  2.2K  [R0402]  33.83 25.6 90 bottom
R113  22R  [R0402]  30.91 23.57 270 bottom
R114  22R  [R0402]  31.88 23.57 270 bottom
R115  22R  [R0402]  32.84 23.57 270 bottom
R116  22R  [R0402]  33.81 23.57 270 bottom
R117  100K  [R0402]  29.21 16.59 0 top
R118  100K  [R0402]  32.31 21.51 180 top
R119  3.9R  [R0603]  25.35 16.33 90 top
R120  3.9R  [R0603]  26.7 16.33 90 top
R121  NC/10K  [R0402]  23.49 47.6 270 top
R122  NC/0R  [RN_0402X4]  16.99 40.51 180 bottom
R123  NC/0R  [RN_0402X4]  16.94 35.97 180 bottom
R126  NC/2.2R  [R0402]  16.97 37.8 180 bottom
R127  NC/2.2R  [R0402]  16.97 38.68 180 bottom
R132  NC/10K  [R0402]  36.02 18.95 270 top
R133  NC/10K  [R0402]  35.51 16.46 0 top
R134  100K  [R0402]  25.86 9.73 90 top
R135  0R  [R0402]  35.51 17.48 180 top
R136  10K  [R0402]  28.37 9.58 90 top
R137  1K  [R0402]  30.91 11.63 90 top
R138  0R  [R0402]  32.72 13.39 180 top
R139  0R  [RN_0402X4]  60.66 14.83 270 top
R140  0R  [RN_0402X4]  54.99 14.66 270 top
R141  NC/0R  [RN_0402X4]  54.94 14.68 270 bottom
R147  2.2R  [R0402]  57.43 14.81 270 top
R148  2.2R  [R0402]  58.32 14.81 270 top
R149  22R  [R0402]  75.54 49.73 270 top
R150  22R  [R0402]  64.97 14.81 270 top
R151  22R  [R0402]  65.86 14.81 270 top
R152  22R  [R0402]  63.96 14.81 270 top
R153  22R  [R0402]  62.94 14.81 270 top
R154  2.2K  [R0402]  62.87 16.84 90 top
R155  2.2K  [R0402]  64.24 16.84 90 top
R156  10K  [R0402]  67.77 14.81 90 top
R157  2.2R  [R0402]  36.42 13.79 270 top
R158  2.2R  [R0402]  37.36 13.79 270 top
R159  NC/22R  [R0402]  44.96 13.49 270 top
R160  NC/22R  [R0402]  43.97 13.49 270 top
R161  10K  [R0402]  43 13.49 90 top
R162  10K  [R0402]  46 15.54 0 top
R163  100R  [R0402]  59.39 50.37 270 top
R164  22R  [R0402]  47.96 15.57 180 top
R165  22R  [R0402]  50.5 15.57 180 top
R166  10K  [R0402]  46.94 13.49 90 top
R172  24.9K  [R0402]  55.83 20.4 270 top
R173  20K  [R0402]  54.81 20.4 90 top
R175  17.4K  [R0402]  60.91 20.4 270 top
R176  20K  [R0402]  59.89 20.4 90 top
R177  49.9K  [R0402]  67.28 20.32 270 top
R179  20K  [R0402]  66.12 20.32 90 top
R180  NC/10K  [R0402]  104.78 28.45 180 top
R181  22R  [R0402]  105.74 27 270 top
R182  22R  [R0402]  104.72 27 270 top
R183  22R  [R0402]  109.6 27 270 top
R184  22R  [R0402]  108.66 27 270 top
R185  NC/10K  [R0402]  107.7 28.91 270 top
R186  22R  [R0402]  107.65 27 270 top
R187  22R  [R0402]  79.55 58.52 270 bottom
R191  NC/0R  [R0402]  114.38 24.08 270 top
R196  0R  [R0402]  110.85 27 270 top
R199  22R  [R0402]  115.14 18.62 180 top
R200  0R  [R0402]  97.23 26.11 270 top
R201  NC/10K  [R0402]  109.04 10.87 0 top
R202  NC/0R  [R0805]  123.01 36.27 180 top
R203  100K  [R0402]  124.41 34.24 90 top
R204  10K  [R0402]  98.63 21.67 0 top
R205  0R  [R0402]  98.63 19.63 0 top
R206  NC/0R  [R0402]  98.63 20.65 0 top
R207  10K  [R0402]  125.43 34.24 90 top
R208  NC/0R  [R0402]  99.14 18.21 270 top
R209  0R  [R0402]  100.69 9.86 90 top
R210  NC/0R  [R0402]  101.6 9.86 90 top
R211  510R  [R0402]  41.1 44.78 180 top
R213  510R  [R0402]  34.37 67.89 270 top
R214  2.2R  [R0402]  30.3 44.91 90 top
R215  2.2R  [R0402]  31.32 44.91 90 top
R216  100R  [R0402]  42.37 39.83 180 top
R219  120R  [R0402]  44.53 39.83 180 top
R220  2.2R  [R0402]  34.87 44.91 90 top
R221  2.2R  [R0402]  35.81 44.91 90 top
R222  2.2R  [R0402]  37.67 44.91 90 top
R223  2.2R  [R0402]  38.61 44.91 90 top
R224  22R  [R0402]  30.81 50.37 270 top
R225  NC/4.7K  [R0402]  39.7 38.13 180 top
R226  4.7K  [R0402]  39.7 37.16 0 top
R227  22R  [R0402]  29.79 50.37 270 top
R228  22R  [R0402]  28.93 64.06 90 top
R229  NC/4.7K  [R0402]  39.7 39.52 180 top
R230  4.7K  [R0402]  44.53 37.16 270 top
R231  22R  [R0402]  28.02 64.06 90 top
R232  22R  [R0402]  28.78 50.37 270 top
R233  4.7K  [R0402]  42.37 36.78 180 top
R234  22R  [R0402]  26.24 64.06 90 top
R235  4.7K  [R0402]  33.1 35 90 top
R236  4.7K  [R0402]  29.06 30.43 270 top
R237  4.7K  [R0402]  34.04 35 90 top
R238  NC/4.7K  [R0402]  33.1 30.43 270 top
R239  4.7K  [R0402]  32.08 35 90 top
R240  NC/4.7K  [R0402]  32.08 30.43 270 top
R241  2.49K  [R0402]  39.7 42.37 180 top
R242  4.7K  [R0402]  31.09 35 90 top
R243  NC/4.7K  [R0402]  31.06 30.43 270 top
R245  NC/4.7K  [R0402]  30.12 35 90 top
R246  4.7K  [R0402]  30.05 30.43 270 top
R248  0R  [R0402]  27.61 41.63 0 top
R249  1.8K  [R0402]  29.67 40.89 0 top
R250  0R  [R0402]  35.89 30.05 180 top
R252  22R  [R0402]  32.08 32.72 270 top
R253  22R  [R0402]  31.06 32.72 270 top
R254  22R  [R0402]  30.05 32.72 270 top
R255  22R  [R0402]  29.03 32.72 270 top
R256  22R  [R0402]  34.11 32.72 270 top
R257  22R  [R0402]  33.1 32.72 270 top
R258  0R  [R0402]  27.64 44.4 0 top
R259  2.2R  [R0402]  56.06 44.91 90 top
R260  2.2R  [R0402]  56.92 44.91 90 top
R261  2.2R  [R0402]  58.62 44.91 90 top
R262  2.2R  [R0402]  59.51 44.91 90 top
R263  2.2R  [R0402]  60.4 44.91 90 top
R264  2.2R  [R0402]  61.42 44.91 90 top
R265  2.2R  [R0402]  63.2 44.91 90 top
R266  2.2R  [R0402]  64.14 44.91 90 top
R267  510R  [R0402]  35.26 67.89 90 top
R268  510R  [R0402]  52.5 75.64 270 top
R270  100R  [R0402]  65.61 38.86 180 top
R271  120R  [R0402]  67.64 37.72 180 top
R272  22R  [R0402]  75.62 64.21 90 top
R273  NC/4.7K  [R0402]  65.61 35.59 180 top
R274  4.7K  [R0402]  67.64 35.76 0 top
R275  22R  [R0402]  74.32 64.21 90 top
R276  22R  [R0402]  79.96 64.21 90 top
R277  NC/4.7K  [R0402]  65.61 37.8 180 top
R278  4.7K  [R0402]  67.64 36.73 0 top
R279  22R  [R0402]  78.69 64.21 90 top
R280  22R  [R0402]  78.94 49.86 270 top
R281  4.7K  [R0402]  65.61 36.58 180 top
R282  22R  [R0402]  77.47 64.21 90 top
R283  4.7K  [R0402]  53.8 32.46 270 top
R284  4.7K  [R0402]  59.79 34.62 90 top
R285  NC/4.7K  [R0402]  60.53 32.84 0 top
R286  4.7K  [R0402]  57.86 34.62 90 top
R287  4.7K  [R0402]  58.27 30.84 180 top
R288  NC/4.7K  [R0402]  56.85 32.46 270 top
R289  2.49K  [R0402]  65.89 44.91 270 top
R290  4.7K  [R0402]  55.83 32.46 90 top
R291  NC/4.7K  [R0402]  56.34 30.3 270 top
R293  NC/4.7K  [R0402]  54.81 32.46 90 top
R294  4.7K  [R0402]  55.32 30.3 270 top
R296  0R  [R0402]  55.12 41.5 0 top
R297  1.8K  [R0402]  55.12 39.32 180 top
R298  0R  [R0402]  62.41 29.82 180 top
R300  22R  [R0402]  56.85 34.62 270 top
R301  22R  [R0402]  55.83 34.62 270 top
R302  22R  [R0402]  54.81 34.62 270 top
R303  22R  [R0402]  53.8 34.62 270 top
R304  22R  [R0402]  58.88 34.62 270 top
R305  22R  [R0402]  57.86 32.46 270 top
R306  0R  [R0402]  68.43 32.87 90 top
R307  NC/2.2R  [R0402]  125.09 21.16 90 top
R308  NC/2.2R  [R0402]  126.01 21.16 90 top
R309  22R  [RN_0402X4]  127.08 42.75 0 top
R310  22R  [RN_0402X4]  127.08 39.57 0 top
R311  22R  [RN_0402X4]  127.94 28.83 0 top
R312  22R  [RN_0402X4]  127.91 24.84 0 top
R314  22R  [R0402]  127.79 26.85 0 top
R315  22R  [RN_0402X4]  126.95 51.13 0 top
R316  22R  [RN_0402X4]  127 48.27 0 top
R326  2.2K  [R0402]  75.97 41.71 180 top
R327  2.2K  [R0402]  75.34 40.28 90 top
R328  22R  [R0402]  76.78 39.78 180 top
R329  22R  [R0402]  76.78 40.72 180 top
R330  100R  [R0402]  121.74 78.56 0 top
R331  15K  [R0402]  112.65 55.55 180 bottom
R332  10K  [R0402]  107.98 57.96 270 bottom
R333  0R  [R0603]  116.41 50.24 270 top
R334  22R  [R0402]  114.71 54.58 180 bottom
R335  22R  [R0402]  114.5 58.06 270 bottom
R336  22R  [R0402]  111.2 57.99 270 bottom
R337  22R  [R0402]  109.68 50.24 270 top
R340  0R  [R0402]  102.59 50.5 270 top
R341  0R  [R0402]  101.6 50.5 270 top
R342  1K  [R0402]  120.93 50.24 90 top
R343  53.6K  [R0402]  98.88 54.69 90 bottom
R344  22R  [R0402]  101.55 54.69 270 bottom
R345  10K  [R0402]  96.95 54.69 270 bottom
R347  22R  [R0402]  50.5 24.84 180 top
R348  22R  [R0402]  50.5 23.7 180 top
R349  22R  [R0402]  50.5 22.81 180 top
R352  22R  [R0402]  50.62 20.9 180 top
R355  2.2R  [R0402]  45.42 26.11 180 top
R356  2.2R  [R0402]  45.42 25.1 180 top
R357  2.2R  [R0402]  43.51 28.14 180 top
R358  2.2R  [R0402]  43.51 27.13 180 top
R359  0R  [R0603]  39.37 27.56 0 top
R360  2.2R  [R0402]  45.42 24.08 180 top
R361  2.2R  [R0402]  45.42 23.06 180 top
R375  2.2R  [R0402]  86.94 69.8 90 top
R376  2.2R  [R0402]  88.21 69.77 90 top
R382  NC/22R  [R0402]  38.28 19.51 180 top
R384  NC/100K  [R0402]  16.46 62.38 180 bottom
R385  NC/100K  [R0402]  16.43 65.05 0 bottom
R387  NC/10K  [R0402]  14.55 13.23 0 top
R388  NC/10K  [R0402]  13.03 15.32 270 top
R389  0R  [R0402]  14.55 14.17 180 top
R390  0R  [R0402]  15.7 17.35 180 top
R391  100K  [R0402]  21.01 53.01 270 bottom
R392  10K  [R0402]  21.92 53.01 270 bottom
R393  1K  [R0402]  20.07 50.39 270 bottom
R394  22R  [R0402]  115.14 17.6 180 top
R398  10K  [R0402]  127.08 37.41 180 top
R399  10K  [R0402]  126.52 31.57 90 top
R400  10K  [R0402]  127.97 31.57 90 top
R401  10K  [R0402]  127.2 35 0 top
R408  NC/0R  [R0402]  22.25 28.91 90 top
R409  0R  [R0402]  21.36 28.91 90 top
R412  100R  [R0402]  76.02 68.53 0 top
R413  NC/0R  [R0402]  90.25 13.92 270 top
R415  0R  [R0402]  89.36 13.92 270 top
R416  22R  [R0402]  55.07 27.13 270 top
R417  22R  [R0402]  23.49 44.15 270 top
R418  22R  [R0402]  74.68 15.88 0 top
R419  1M  [R0805]  14.81 71.27 90 bottom
R421  120R  [R0402]  58.5 50.37 270 top
R422  NC/0R  [R0402]  88.11 67.61 270 top
R423  NC/0R  [R0402]  87.12 67.61 270 top
R424  2.2R  [R0402]  33.1 44.91 90 top
R425  2.2R  [R0402]  33.99 44.91 90 top
SIM1  SIM  [SIM-91288-021]  119.96 61.42 270 bottom
SW1  T-switch  [PB-SIDE-S-3_5X4_5]  127.97 87.96 0 bottom
SW2  T-switch  [PB-SIDE-S-3_5X4_5]  86.46 87.99 0 bottom
U1  ETA1654FSG  [SOT563]  68.28 67.89 0 top
U2  ETA1654FSG  [SOT563]  18.87 28.02 0 top
U3  ETA3417S2F  [SOT23-5]  28.14 25.22 180 top
U4  SY6280AAC  [SOT23-5]  120.98 52.15 270 bottom
U5  SY6280AAC  [SOT23-5]  94.77 70.08 270 top
U6  SY6280AAC  [SOT23-5]  93.42 66.24 0 top
U7  SY6280AAC  [SOT23-5]  121.36 21.16 90 top
U8  FE1.1  [LQFP-48_7X7X05P]  107.01 39.7 90 top
U9  SY6280AAC  [SOT23-5]  107.77 8.2 180 top
U10  SY6280AAC  [SOT23-5]  98.25 14.81 90 top
U11  NS4205  [SOP16-P127-390X990]  112.85 73.1 0 top
U12  SY7201ABC  [SOT23-6]  85.42 23.7 180 top
U13  SY7201ABC  [SOT23-6]  29.54 19.63 90 top
U14  NC/74LVC1G125GW,125  [SOT353]  29.79 13.79 0 top
U15  ETA5050V0S2F  [SOT23-5]  56.68 23.65 270 top
U16  ETA5050V0S2F  [SOT23-5]  61.8 23.83 270 top
U17  ETA5050V0S2F  [SOT23-5]  67.33 23.8 270 top
U18  AP6236  MODULE  [WIFI_44P_12X12]  106.76 18.62 180 top
U19  RTL8211F-CG  [QFN-40_5X5X04P]  34.75 40.21 270 top
U20  RTL8211F-CG  [QFN-40_5X5X04P]  60.02 40.08 270 top
U21  HYM8563S  [TSSOP-8]  77.75 36.14 90 top
U22  ETA3417  [SOT23-5]  100.15 51.89 180 bottom
U25  NC/74LVC1G125GW,125  [SOT353]  12.49 17.98 0 top
XT1  12MHz  [XTAL_32X25_4P]  114 32.33 0 top
XT2  NC/26MHz  [XTAL_32X25_4P]  116.84 26.34 90 top
XT3  25MHz  [XTAL_32X25_4P]  44.27 42.62 0 top
XT4  25MHz  [XTAL_32X25_4P]  67.89 41.35 0 top
XT5  32.768KHz  [XTAL_32X15_2P]  77.34 30.05 180 top

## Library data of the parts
C1 C7 C8 C12 C13 C16 C17 C23 C24 C30 C35 C39 C41 C48 C49 C51 C55-C68 C71-C78 C80 C82 C83 C85 C88-C90 C95-C100 C103 C104 C107 C108 C111-C117 C120-C124 C126-C176 C179-C189 C194 C199-C204 C206 C207 C212 C213 C233-C242 C253-C255 C258-C260 C290 C291 = C-0402
C2 C4-C6 C9-C11 C14 C15 C18-C20 C26-C29 C91 C93 C245 C247-C252 C256 C257 = C-0805
C3 = C-AL-SMD
C21 C22 C25 C31-C34 C36-C38 C40 C42-C47 C50 C52-C54 C79 C81 C84 C86 C87 C92 C94 C101 C102 C105 C106 C109 C110 C118 C119 C125 C177 C190-C193 C195-C198 C205 C208 C209 C214-C222 C243 C244 C246 = C-0603
C261 = C-1206
D1 D54-D61 = DI-TVS-D
D2 D5-D10 D12 D15 D16 D18-D33 D36 D38 D44-D47 D52 D53 D64 D65 D71-D75 D79 D80 D96 D97 D100 D101 D105 D106 = DI-ESD
D3 D4 D14 D17 D34 D35 D37 D40 D41 D48 D49 D51 D76 D77 D98 D99 D102-D104 D107 = DI-ESD-SE05NRC14GA
D11 D13 D39 D42 D43 D50 D69 D70 D90 = DI-XI-S
D81-D84 = DI-ESD-SRV05-4
F2 = FUSE-SMD1812: User Part Number: HAMP; Tolerance: #TOL
H1 = HOLE: Tolerance: RichardLC; User Part Number: pn
H2 = HOLE: User Part Number: pn; Tolerance: RichardLC
HOLE1-HOLE4 = MH-NOE: User Part Number: pn; Tolerance: RichardLC
J1 = J-DC-044A-2_5
J2 = ATMD097-AED4S-5F_5
J3 = J-TF-01A
J4 = J-A-3P
J5 = J-TYPE_C_16P
J6 = J-USB-9AFx2-DIP-W
J7-J9 J12 J32 = J-H-4P
J10 = J-PJ-326A-3P
J11 = J-H-2P
J13 J15 = J-FPC-40P
J14 = J-HDMI-19P
J16 J28 = J-HDR-D-20: User Part Number: pn; Tolerance: RichardLC
J17 J29 = J-HDR-6: User Part Number: pn; Tolerance: RichardLC
J18 J30 = J-H-6P
J19 J20 = J-FPC-24P
J21 = RF-IPEX-20279
J22 J23 = J-RJ45-HR911130C: User Part Number: HAMP; Tolerance: #TOL
J24 = J-HDR-D-40_0: User Part Number: pn; Tolerance: RichardLC
J25 = J-A-2P
J26 = J-MINIPCIE-52P_1
J27 = J-M2_NGFF-M-KEY_1
J31 = J-FPC-6P
L1 = L-CMLP
L2-L4 L15 L20-L24 = L-IND
L5-L10 L16-L19 = L-CMLS-ACM2012
L11-L14 = FB-0603
LED1 = D-LED-DIP-2: User Part Number: DENG
LED2 = D-LED0603_0
MARK1 MARK2 MARK4 = MARK-FID10X20_1
MARK3 = MARK-FID10X20_0
Q1-Q5 Q7 Q8 Q11 Q13-Q17 Q19 = N-MOS-Q
Q6 Q10 Q12 = P-MOS
R1 R2 R17 R86 R202 R419 = R-0805
R3-R16 R18-R43 R45-R49 R51-R61 R64-R84 R87-R100 R103-R118 R121 R126 R127 R132-R138 R147-R166 R172 R173 R175-R177 R179-R187 R191 R196 R199-R201 R203-R211 R213-R216 R219-R243 R245 R246 R248-R250 R252-R268 R270-R291 R293 R294 R296-R298 R300-R308 R314 R326-R332 R334-R337 R340-R345 R347-R349 R352 R355-R358 R360 R361 R375 R376 R382 R384 R385 R387-R394 R398-R401 R408 R409 R412 R413 R415-R418 R421-R425 = R-0402
R85 R101 R102 R119 R120 R333 R359 = R-0603
R122 R123 R139-R141 R309-R312 R315 R316 = RN_0402X4
SIM1 = J-SIM-021_0
SW1 SW2 = SW-TS24CA
U1 U2 = U-ETA1654FSG
U3 = U-ETA3417S2F
U4-U7 U9 U10 = U-SY6280AAC_1
U8 = U-FE2_0.1: User Part Number: HAMP; Tolerance: #TOL
U11 = U-NS4205
U12 U13 = U-SY7201A_2
U14 U25 = U-74LVC1G125GW-125
U15-U17 = U-ETA5050
U18 = MODULE_AP6XXX
U19 U20 = Ethernet_RTL8211F
U21 = U-HYM8563S
U22 = U-ETA3417_1
XT1-XT4 = XTAL-4P
XT5 = XTAL-2P

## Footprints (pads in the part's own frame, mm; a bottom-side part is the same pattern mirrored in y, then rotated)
4G_MTG170_450
  round 4.5 hole 1.7: 1(0,0)
C0402
  rect 0.55x0.55 smd: 1(-0.45,0) 2(0.45,0)
C0603
  rect 0.8x0.9 smd: 1(-0.7,0) 2(0.7,0)
C0805
  rect 0.95x1.3 smd: 1(-0.825,0) 2(0.825,0)
C1206
  rect 1.4x1.6 smd: 1(-1.168,0) 2(1.168,0)
CAPAE660X770
  rect 3.15x1.6 smd: 1(-2.45,0) 2(2.45,0)
CMLP-ACM4532
  rect 1.5x1.3 smd: 1(-1.5,0.95) 2(-1.5,-0.95) 3(1.5,-0.95) 4(1.5,0.95)
CMLS-ACM2012
  rect 0.7x0.45 smd: 1(-0.85,0.4) 2(-0.85,-0.4) 3(0.85,-0.4) 4(0.85,0.4)
DC-044A-2_0-DIP
  round 2.3 hole 2.3 unplated: (4.1,0)
  rect 3x1.6 hole 2x0.8: 2(10.201,5.199) 3(10.201,0) 4(10.201,-3.401)
  rect 2.5x1 hole 2x0.6: 5(3,6.149) 6(3,-3.65)
DDR4-SODIMM-260P-STD
  round 1.6 hole 1.6 unplated: (0,0)
  round 1.1 hole 1.1 unplated: (68.8,0)
  rect 0.25x1.75 smd: 1(1.025,-4.1) 2(1.275,4.1) 3(1.525,-4.1) 4(1.775,4.1) 5(2.025,-4.1) 6(2.275,4.1) 7(2.525,-4.1) 8(2.775,4.1) 9(3.025,-4.1) 10(3.275,4.1) 11(3.525,-4.1) 12(3.775,4.1) 13(4.025,-4.1) 14(4.275,4.1) 15(4.525,-4.1) 16(4.775,4.1) 17(5.025,-4.1) 18(5.275,4.1) 19(5.525,-4.1) 20(5.775,4.1) 21(6.025,-4.1) 22(6.275,4.1) 23(6.525,-4.1) 24(6.775,4.1) 25(7.025,-4.1) 26(7.275,4.1) 27(7.525,-4.1) 28(7.775,4.1) 29(8.025,-4.1) 30(8.275,4.1) 31(8.525,-4.1) 32(8.775,4.1) 33(9.025,-4.1) 34(9.275,4.1) 35(9.525,-4.1) 36(9.775,4.1) 37(10.025,-4.1) 38(10.275,4.1) 39(10.525,-4.1) 40(10.775,4.1) 41(11.025,-4.1) 42(11.275,4.1) 43(11.525,-4.1) 44(11.775,4.1) 45(12.025,-4.1) 46(12.275,4.1) 47(12.525,-4.1) 48(12.775,4.1) 49(13.025,-4.1) 50(13.275,4.1) 51(13.525,-4.1) 52(13.775,4.1) 53(14.025,-4.1) 54(14.275,4.1) 55(14.525,-4.1) 56(14.775,4.1) 57(15.025,-4.1) 58(15.275,4.1) 59(15.525,-4.1) 60(15.775,4.1) 61(16.025,-4.1) 62(16.275,4.1) 63(16.525,-4.1) 64(16.775,4.1) 65(17.025,-4.1) 66(17.275,4.1) 67(17.525,-4.1) 68(17.775,4.1) 69(18.025,-4.1) 70(18.275,4.1) 71(18.525,-4.1) 72(18.775,4.1) 73(19.025,-4.1) 74(19.275,4.1) 75(19.525,-4.1) 76(19.775,4.1) 77(20.025,-4.1) 78(20.275,4.1) 79(20.525,-4.1) 80(20.775,4.1) 81(21.025,-4.1) 82(21.275,4.1) 83(21.525,-4.1) 84(21.775,4.1) 85(22.025,-4.1) 86(22.275,4.1) 87(22.525,-4.1) 88(22.775,4.1) 89(23.025,-4.1) 90(23.275,4.1) 91(23.525,-4.1) 92(23.775,4.1) 93(24.025,-4.1) 94(24.275,4.1) 95(24.525,-4.1) 96(24.775,4.1) 97(25.025,-4.1) 98(25.275,4.1) 99(25.525,-4.1) 100(25.775,4.1) 101(26.025,-4.1) 102(26.275,4.1) 103(26.525,-4.1) 104(26.775,4.1) 105(27.025,-4.1) 106(27.275,4.1) 107(27.525,-4.1) 108(27.775,4.1) 109(28.025,-4.1) 110(28.275,4.1) 111(28.525,-4.1) 112(28.775,4.1) 113(29.025,-4.1) 114(29.275,4.1) 115(29.525,-4.1) 116(29.775,4.1) 117(30.025,-4.1) 118(30.275,4.1) 119(30.525,-4.1) 120(30.775,4.1) 121(31.025,-4.1) 122(31.275,4.1) 123(31.525,-4.1) 124(31.775,4.1) 125(32.025,-4.1) 126(32.275,4.1) 127(32.525,-4.1) 128(32.775,4.1) 129(33.025,-4.1) 130(33.275,4.1) 131(33.525,-4.1) 132(33.775,4.1) 133(34.025,-4.1) 134(34.275,4.1) 135(34.525,-4.1) 136(34.775,4.1) 137(35.025,-4.1) 138(35.275,4.1) 139(35.525,-4.1) 140(35.775,4.1) 141(36.025,-4.1) 142(36.275,4.1) 143(36.525,-4.1) 144(36.775,4.1) 145(39.025,-4.1) 146(39.275,4.1) 147(39.525,-4.1) 148(39.775,4.1) 149(40.025,-4.1) 150(40.275,4.1) 151(40.525,-4.1) 152(40.775,4.1) 153(41.025,-4.1) 154(41.275,4.1) 155(41.525,-4.1) 156(41.775,4.1) 157(42.025,-4.1) 158(42.275,4.1) 159(42.525,-4.1) 160(42.775,4.1) 161(43.025,-4.1) 162(43.275,4.1) 163(43.525,-4.1) 164(43.775,4.1) 165(44.025,-4.1) 166(44.275,4.1) 167(44.525,-4.1) 168(44.775,4.1) 169(45.025,-4.1) 170(45.275,4.1) 171(45.525,-4.1) 172(45.775,4.1) 173(46.025,-4.1) 174(46.275,4.1) 175(46.525,-4.1) 176(46.775,4.1) 177(47.025,-4.1) 178(47.275,4.1) 179(47.525,-4.1) 180(47.775,4.1) 181(48.025,-4.1) 182(48.275,4.1) 183(48.525,-4.1) 184(48.775,4.1) 185(49.025,-4.1) 186(49.275,4.1) 187(49.525,-4.1) 188(49.775,4.1) 189(50.025,-4.1) 190(50.275,4.1) 191(50.525,-4.1) 192(50.775,4.1) 193(51.025,-4.1) 194(51.275,4.1) 195(51.525,-4.1) 196(51.775,4.1) 197(52.025,-4.1) 198(52.275,4.1) 199(52.525,-4.1) 200(52.775,4.1) 201(53.025,-4.1) 202(53.275,4.1) 203(53.525,-4.1) 204(53.775,4.1) 205(54.025,-4.1) 206(54.275,4.1) 207(54.525,-4.1) 208(54.775,4.1) 209(55.025,-4.1) 210(55.275,4.1) 211(55.525,-4.1) 212(55.775,4.1) 213(56.025,-4.1) 214(56.275,4.1) 215(56.525,-4.1) 216(56.775,4.1) 217(57.025,-4.1) 218(57.275,4.1) 219(57.525,-4.1) 220(57.775,4.1) 221(58.025,-4.1) 222(58.275,4.1) 223(58.525,-4.1) 224(58.775,4.1) 225(59.025,-4.1) 226(59.275,4.1) 227(59.525,-4.1) 228(59.775,4.1) 229(60.025,-4.1) 230(60.275,4.1) 231(60.525,-4.1) 232(60.775,4.1) 233(61.025,-4.1) 234(61.275,4.1) 235(61.525,-4.1) 236(61.775,4.1) 237(62.025,-4.1) 238(62.275,4.1) 239(62.525,-4.1) 240(62.775,4.1) 241(63.025,-4.1) 242(63.275,4.1) 243(63.525,-4.1) 244(63.775,4.1) 245(64.025,-4.1) 246(64.275,4.1) 247(64.525,-4.1) 248(64.775,4.1) 249(65.025,-4.1) 250(65.275,4.1) 251(65.525,-4.1) 252(65.775,4.1) 253(66.025,-4.1) 254(66.275,4.1) 255(66.525,-4.1) 256(66.775,4.1) 257(67.025,-4.1) 258(67.275,4.1) 259(67.525,-4.1) 260(67.775,4.1)
  rect 3.505x4.597 smd: N1(0.6,12) N2(68.2,12)
  round 5 hole 2.2: N3(2,42.3) N4(66.8,42.3)
DFN2510-10L
  rect 0.2x0.68 smd: 1(-1,-0.437) 2(-0.5,-0.437) 4(0.5,-0.437) 5(1,-0.437) 6(1,0.437) 7(0.5,0.437) 9(-0.5,0.437) 10(-1,0.437)
  rect 0.4x0.75 smd: 3(0,-0.395) 8(0,0.395)
FID1_0X2_3
  round 1 smd: 1(0,0)
FPC05-6P
  rect 0.305x1.27 smd: 1(1.25,1.575) 2(0.75,1.575) 3(0.25,1.575) 4(-0.25,1.575) 5(-0.75,1.575) 6(-1.25,1.575)
  rect 1.803x3.048 smd: 7(2.95,-0.8) 8(-2.95,-0.8)
FPC05-24P
  rect 0.305x1.27 smd: 1(5.75,1.575) 2(5.25,1.575) 3(4.75,1.575) 4(4.25,1.575) 5(3.75,1.575) 6(3.25,1.575) 7(2.75,1.575) 8(2.25,1.575) 9(1.75,1.575) 10(1.25,1.575) 11(0.75,1.575) 12(0.25,1.575) 13(-0.25,1.575) 14(-0.75,1.575) 15(-1.25,1.575) 16(-1.75,1.575) 17(-2.25,1.575) 18(-2.75,1.575) 19(-3.25,1.575) 20(-3.75,1.575) 21(-4.25,1.575) 22(-4.75,1.575) 23(-5.25,1.575) 24(-5.75,1.575)
  rect 1.803x3.048 smd: 25(7.45,-0.8) 26(-7.45,-0.8)
FPC05-40P
  rect 0.305x1.27 smd: 1(9.75,1.575) 2(9.25,1.575) 3(8.75,1.575) 4(8.25,1.575) 5(7.75,1.575) 6(7.25,1.575) 7(6.75,1.575) 8(6.25,1.575) 9(5.75,1.575) 10(5.25,1.575) 11(4.75,1.575) 12(4.25,1.575) 13(3.75,1.575) 14(3.25,1.575) 15(2.75,1.575) 16(2.25,1.575) 17(1.75,1.575) 18(1.25,1.575) 19(0.75,1.575) 20(0.25,1.575) 21(-0.25,1.575) 22(-0.75,1.575) 23(-1.25,1.575) 24(-1.75,1.575) 25(-2.25,1.575) 26(-2.75,1.575) 27(-3.25,1.575) 28(-3.75,1.575) 29(-4.25,1.575) 30(-4.75,1.575) 31(-5.25,1.575) 32(-5.75,1.575) 33(-6.25,1.575) 34(-6.75,1.575) 35(-7.25,1.575) 36(-7.75,1.575) 37(-8.25,1.575) 38(-8.75,1.575) 39(-9.25,1.575) 40(-9.75,1.575)
  rect 1.803x3.048 smd: 41(11.45,-0.8) 42(-11.45,-0.8)
HDMI-TYPEA_SMD
  rect 0.3x2.6 smd: 1(0,0) 2(0.5,0) 3(1,0) 4(1.5,0) 5(2,0) 6(2.5,0) 7(3,0) 8(3.5,0) 9(4,0) 10(4.5,0) 11(5,0) 12(5.5,0) 13(6,0) 14(6.5,0) 15(7,0) 16(7.5,0) 17(8,0) 18(8.5,0) 19(9,0)
  oval 1.2x3 hole 0.7x2.4: 20(11.75,0.76) 21(-2.75,0.76)
  oval 1.2x2 hole 0.7x1.4: 22(-2.75,6.72) 23(11.75,6.72)
HDR200MA-1X6
  rect 1.3x1.3 hole 0.8: 1(0,0)
  round 1.3 hole 0.8: 2(2,0) 3(4,0) 4(6,0) 5(8,0) 6(10,0)
HDR200MRA-2X10
  rect 1.5x1.5 hole 0.7: 1(0,0)
  round 1.3 hole 0.7: 2(0,2) 3(2,0) 4(2,2) 5(4,0) 6(4,2) 7(6,0) 8(6,2) 9(8,0) 10(8,2) 11(10,0) 12(10,2) 13(12,0) 14(12,2) 15(14,0) 16(14,2) 17(16,0) 18(16,2) 19(18,0) 20(18,2)
HDR254MA-2X18
  rect 1.7x1.7 hole 1: 1(0,0)
  round 1.7 hole 1: 2(0,2.54) 3(2.54,0) 4(2.54,2.54) 5(5.08,0) 6(5.08,2.54) 7(7.62,0) 8(7.62,2.54) 9(10.16,0) 10(10.16,2.54) 11(12.7,0) 12(12.7,2.54) 13(15.24,0) 14(15.24,2.54) 15(17.78,0) 16(17.78,2.54) 17(20.32,0) 18(20.32,2.54) 19(22.86,0) 20(22.86,2.54) 21(25.4,0) 22(25.4,2.54) 23(27.94,0) 24(27.94,2.54) 25(30.48,0) 26(30.48,2.54) 27(33.02,0) 28(33.02,2.54) 29(35.56,0) 30(35.56,2.54) 31(38.1,0) 32(38.1,2.54) 33(40.64,0) 34(40.64,2.54) 35(43.18,0) 36(43.18,2.54)
IND_252012
  rect 0.7x2 smd: 1(-1.05,0) 2(1.05,0)
IND_404020
  rect 1.5x4 smd: 1(-1.5,0) 2(1.5,0)
IPEX-001E
  rect 1.2x0.8 smd: 1(-1.525,0)
  rect 1.5x1.2 smd: 2(1.8,0)
  rect 2.65x1.2 smd: 3(0,-1.5) 4(0,1.5)
L0603
  rect 0.75x0.9 smd: 1(-0.7,0) 2(0.7,0)
LED0603
  rect 0.9x0.9 smd: 1(-0.8,0) 2(0.8,0)
LED_P254_2X2DIP
  round 1.422 hole 0.914: 1(-1.27,-1.27) 2(1.27,-1.27) 3(-1.27,1.27) 4(1.27,1.27)
LQFP-48_7X7X05P
  oval 1.651x0.279 smd: 1(-4.275,2.751) 2(-4.275,2.25) 3(-4.275,1.75) 4(-4.275,1.25) 5(-4.275,0.749) 6(-4.275,0.249) 7(-4.275,-0.249) 8(-4.275,-0.749) 9(-4.275,-1.25) 10(-4.275,-1.75) 11(-4.275,-2.25) 12(-4.275,-2.751) 25(4.275,-2.751) 26(4.275,-2.25) 27(4.275,-1.75) 28(4.275,-1.25) 29(4.275,-0.749) 30(4.275,-0.249) 31(4.275,0.249) 32(4.275,0.749) 33(4.275,1.25) 34(4.275,1.75) 35(4.275,2.25) 36(4.275,2.751)
  oval 0.279x1.651 smd: 13(-2.751,-4.275) 14(-2.25,-4.275) 15(-1.75,-4.275) 16(-1.25,-4.275) 17(-0.749,-4.275) 18(-0.249,-4.275) 19(0.249,-4.275) 20(0.749,-4.275) 21(1.25,-4.275) 22(1.75,-4.275) 23(2.25,-4.275) 24(2.751,-4.275) 37(2.751,4.275) 38(2.25,4.275) 39(1.75,4.275) 40(1.25,4.275) 41(0.749,4.275) 42(0.249,4.275) 43(-0.249,4.275) 44(-0.749,4.275) 45(-1.25,4.275) 46(-1.75,4.275) 47(-2.25,4.275) 48(-2.751,4.275)
M2_NGFF-M-KEY
  round 1.118 hole 1.118 unplated: (0,-10)
  round 1.6 hole 1.6 unplated: (0,10)
  rect 1.6x0.3 smd: 1(-4.725,-9.25) 2(1.725,-9) 3(-4.725,-8.75) 4(1.725,-8.5) 5(-4.725,-8.25) 6(1.725,-8) 7(-4.725,-7.75) 8(1.725,-7.5) 9(-4.725,-7.25) 10(1.725,-7) 11(-4.725,-6.75) 12(1.725,-6.5) 13(-4.725,-6.25) 14(1.725,-6) 15(-4.725,-5.75) 16(1.725,-5.5) 17(-4.725,-5.25) 18(1.725,-5) 19(-4.725,-4.75) 20(1.725,-4.5) 21(-4.725,-4.25) 22(1.725,-4) 23(-4.725,-3.75) 24(1.725,-3.5) 25(-4.725,-3.25) 26(1.725,-3) 27(-4.725,-2.75) 28(1.725,-2.5) 29(-4.725,-2.25) 30(1.725,-2) 31(-4.725,-1.75) 32(1.725,-1.5) 33(-4.725,-1.25) 34(1.725,-1) 35(-4.725,-0.75) 36(1.725,-0.5) 37(-4.725,-0.25) 38(1.725,0) 39(-4.725,0.25) 40(1.725,0.5) 41(-4.725,0.75) 42(1.725,1) 43(-4.725,1.25) 44(1.725,1.5) 45(-4.725,1.75) 46(1.725,2) 47(-4.725,2.25) 48(1.725,2.5) 49(-4.725,2.75) 50(1.725,3) 51(-4.725,3.25) 52(1.725,3.5) 53(-4.725,3.75) 54(1.725,4) 55(-4.725,4.25) 56(1.725,4.5) 57(-4.725,4.75) 58(1.725,5) 67(-4.725,7.25) 68(1.725,7.5) 69(-4.725,7.75) 70(1.725,8) 71(-4.725,8.25) 72(1.725,8.5) 73(-4.725,8.75) 74(1.725,9) 75(-4.725,9.25)
  rect 2.8x1.2 smd: G1(-4.5,10.35) G2(-4.5,-10.35)
  round 4.5 hole 2.6: G3(77.8,0) G4(44.6,0)
